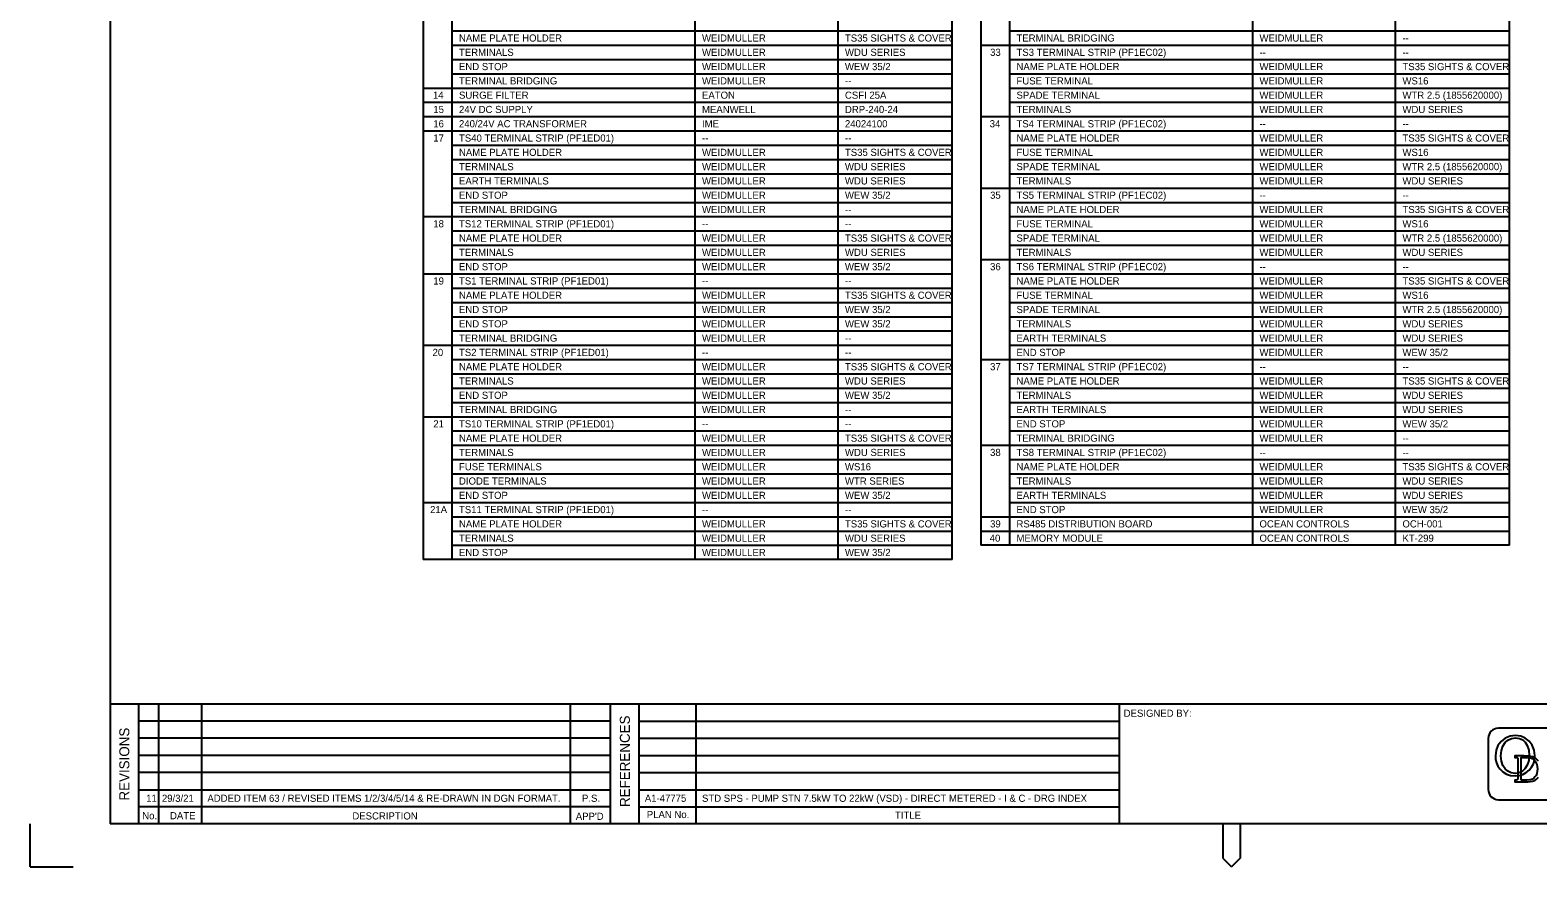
# Model space of a CAD drawing. Extents: x 0 to 841, y 0 to 594.
# Drawn here: x 0 to 527, y 0 to 293 of the extents above; entities that cross this region are included whole.
import ezdxf

# ---------------------------------------------------------------- set-up
doc = ezdxf.new("R2010")
doc.units = 0
for name, color, linetype in [('A1BORDER', 7, 'Continuous'), ('Default', 7, 'Continuous'), ('Level 1', 7, 'Continuous'), ('Level 10', 7, 'Continuous')]:
    doc.layers.add(name, color=color, linetype=linetype)

msp = doc.modelspace()

# ---------------------------------------------------------------- linework, layer by layer
at = {"layer": 'A1BORDER'}
for p, q in [((28, 581), (28, 15)), ((28, 57), (829, 57)), ((38, 15), (38, 57)), ((45, 15), (45, 57)), ((60, 15), (60, 57)), ((189, 15), (189, 57)), ((203, 15), (203, 57)), ((213, 15), (213, 57)), ((233, 15), (233, 57)), ((381, 15), (381, 57)), ((203, 51), (38, 51)), ((213, 51), (381, 51)), ((203, 45), (38, 45)), ((213, 45), (381, 45)), ((203, 39), (38, 39)), ((213, 39), (381, 39)), ((203, 33), (38, 33)), ((213, 33), (381, 33)), ((38, 27), (203, 27)), ((213, 27), (381, 27)), ((203, 21), (38, 21)), ((213, 21), (381, 21)), ((0, 0), (0, 15)), ((829, 15), (28, 15)), ((417.19, 15), (417.19, 3)), ((423.19, 15), (423.19, 3)), ((417.19, 3), (420.19, 0)), ((423.19, 3), (420.19, 0)), ((0, 0), (15, 0))]:
    msp.add_line(p, q, dxfattribs=at)
at = {"layer": 'Default'}
for p, q in [((342.5, 292.5), (517.5, 292.5)), ((332.5, 287.5), (517.5, 287.5)), ((342.5, 282.5), (517.5, 282.5)), ((342.5, 277.5), (517.5, 277.5)), ((342.5, 272.5), (517.5, 272.5)), ((342.5, 267.5), (517.5, 267.5)), ((332.5, 262.5), (517.5, 262.5)), ((342.5, 257.5), (517.5, 257.5)), ((342.5, 252.5), (517.5, 252.5)), ((342.5, 247.5), (517.5, 247.5)), ((332.5, 237.5), (517.5, 237.5)), ((342.5, 242.5), (517.5, 242.5)), ((342.5, 232.5), (517.5, 232.5)), ((342.5, 227.5), (517.5, 227.5)), ((342.5, 222.5), (517.5, 222.5)), ((342.5, 217.5), (517.5, 217.5)), ((332.5, 212.5), (517.5, 212.5)), ((342.5, 207.5), (517.5, 207.5)), ((342.5, 202.5), (517.5, 202.5)), ((342.5, 197.5), (517.5, 197.5)), ((342.5, 192.5), (517.5, 192.5)), ((342.5, 187.5), (517.5, 187.5)), ((342.5, 182.5), (517.5, 182.5)), ((332.5, 177.5), (517.5, 177.5)), ((342.5, 172.5), (517.5, 172.5)), ((342.5, 167.5), (517.5, 167.5)), ((342.5, 162.5), (517.5, 162.5)), ((342.5, 157.5), (517.5, 157.5)), ((342.5, 152.5), (517.5, 152.5)), ((332.5, 147.5), (517.5, 147.5)), ((342.5, 142.5), (517.5, 142.5)), ((342.5, 137.5), (517.5, 137.5)), ((342.5, 132.5), (517.5, 132.5)), ((342.5, 127.5), (517.5, 127.5))]:
    msp.add_line(p, q, dxfattribs=at)
at = {"layer": 'Level 1'}
for p, q in [((137.5, 546), (137.5, 107.5)), ((322.5, 107.5), (322.5, 546)), ((332.5, 546), (332.5, 112.5)), ((517.5, 112.5), (517.5, 546)), ((147.5, 536.25), (147.5, 107.5)), ((232.5, 536.25), (232.5, 107.5)), ((282.5, 536.25), (282.5, 107.5)), ((342.5, 536.25), (342.5, 112.5)), ((427.5, 536.25), (427.5, 112.5)), ((477.5, 536.25), (477.5, 112.5)), ((147.5, 292.5), (322.5, 292.5)), ((147.5, 287.5), (322.5, 287.5)), ((147.5, 282.5), (322.5, 282.5)), ((147.5, 277.5), (322.5, 277.5)), ((137.5, 272.5), (322.5, 272.5)), ((137.5, 267.5), (322.5, 267.5)), ((137.5, 262.5), (322.5, 262.5)), ((137.5, 257.5), (322.5, 257.5)), ((147.5, 252.5), (322.5, 252.5)), ((147.5, 247.5), (322.5, 247.5)), ((147.5, 242.5), (322.5, 242.5)), ((147.5, 237.5), (322.5, 237.5)), ((147.5, 232.5), (322.5, 232.5)), ((137.5, 227.5), (322.5, 227.5)), ((147.5, 222.5), (322.5, 222.5)), ((147.5, 217.5), (322.5, 217.5)), ((147.5, 212.5), (322.5, 212.5)), ((137.5, 207.5), (322.5, 207.5)), ((147.5, 202.5), (322.5, 202.5)), ((147.5, 197.5), (322.5, 197.5)), ((147.5, 192.5), (322.5, 192.5)), ((147.5, 187.5), (322.5, 187.5)), ((137.5, 182.5), (322.5, 182.5)), ((147.5, 177.5), (322.5, 177.5)), ((147.5, 172.5), (322.5, 172.5)), ((147.5, 167.5), (322.5, 167.5)), ((147.5, 162.5), (322.5, 162.5)), ((137.5, 157.5), (322.5, 157.5)), ((147.5, 152.5), (322.5, 152.5)), ((147.5, 147.5), (322.5, 147.5)), ((147.5, 142.5), (322.5, 142.5)), ((147.5, 137.5), (322.5, 137.5)), ((147.5, 132.5), (322.5, 132.5)), ((137.5, 127.5), (322.5, 127.5)), ((147.5, 122.5), (322.5, 122.5)), ((332.5, 122.5), (517.5, 122.5)), ((147.5, 117.5), (322.5, 117.5)), ((332.5, 117.5), (517.5, 117.5)), ((147.5, 112.5), (322.5, 112.5)), ((517.5, 112.5), (332.5, 112.5)), ((322.5, 107.5), (137.5, 107.5))]:
    msp.add_line(p, q, dxfattribs=at)
for points in [[(519.59, 45.93), (517.69, 45.7), (515.96, 45), (514.48, 43.9), (513.4, 42.47), (512.73, 40.77), (512.5, 38.87), (512.6, 37.57), (512.9, 36.37), (513.39, 35.25), (514.1, 34.25), (515.17, 33.2), (516.4, 32.45), (517.82, 32), (519.4, 31.87), (520.84, 32), (522.14, 32.35), (523.32, 32.97), (524.34, 33.83), (525.19, 34.9), (525.8, 36.1), (526.17, 37.45), (526.28, 38.95), (526.07, 40.85), (525.42, 42.53), (524.37, 43.93), (522.94, 45.03), (521.36, 45.7)], [(519.6, 45.1), (520.96, 44.93), (522.06, 44.45), (522.96, 43.63), (523.66, 42.47), (524.18, 40.8), (524.36, 39), (524.18, 37.23), (523.66, 35.63), (522.86, 34.3), (521.88, 33.4), (520.73, 32.87), (519.42, 32.7), (518.08, 32.87), (516.88, 33.43), (515.88, 34.3), (515.1, 35.5), (514.59, 37), (514.43, 38.83), (514.59, 40.7), (515.1, 42.27), (515.89, 43.5), (516.9, 44.37), (518.14, 44.93)], [(521.52, 30.35), (521.52, 38.25), (522.88, 38.25), (524.09, 38.23), (524.74, 38.1), (525.32, 37.87), (525.84, 37.53), (526.32, 37.05), (526.7, 36.5), (526.99, 35.85), (527.16, 35.13), (527.22, 34.27), (527.16, 33.43), (526.99, 32.67), (526.72, 32), (526.36, 31.45), (525.93, 31.03), (525.5, 30.73), (524.52, 30.45), (523.5, 30.35)]]:
    msp.add_lwpolyline(points, close=True, dxfattribs=at)
msp.add_lwpolyline([(527.62, 37), (527.18, 37.5), (526.7, 37.95), (526.16, 38.27), (525.54, 38.53), (524.36, 38.73), (522.5, 38.8), (519.3, 38.8), (519.3, 38.25), (520.07, 38.23), (520.34, 38), (520.4, 37.5), (520.4, 31.07), (520.36, 30.63), (520.16, 30.43), (519.78, 30.35), (519.67, 30.35), (519.3, 30.35), (519.3, 29.8), (523.88, 29.8), (524.7, 29.85), (525.53, 30), (526.28, 30.25), (526.93, 30.67), (527.56, 31.33)], dxfattribs=at)
at = {"layer": 'Level 10'}
for p, q in [((571.47, 48.5), (513.54, 48.5)), ((510, 44.97), (510, 27.03)), ((513.54, 23.5), (571.47, 23.5)), ((513.54, 23.5), (513.54, 23.5))]:
    msp.add_line(p, q, dxfattribs=at)
for centre, start, end in [((513.54, 44.96), 90, 180), ((513.54, 27.03), 180, 270)]:
    msp.add_arc(centre, 3.54, start, end, dxfattribs=at)

# ---------------------------------------------------------------- texts
at = {"layer": 'A1BORDER'}
for s, p in [('DESIGNED BY:', (382.5, 52.5)), ('No.', (39.21, 16.65)), ('DATE', (48.92, 16.65)), ('DESCRIPTION', (112.71, 16.57)), ("APP'D", (190.85, 16.44)), ('PLAN No.', (215.69, 17.06)), ('TITLE', (302.5, 16.81))]:
    msp.add_text(s, height=2.5, dxfattribs=at).set_placement(p)
for s, p in [('REVISIONS', (34.68, 23.2)), ('REFERENCES', (209.76, 20.96))]:
    msp.add_text(s, height=3.5, rotation=90, dxfattribs=at).set_placement(p)
at = {"layer": 'Default'}
for s, p in [('TERMINAL BRIDGING', (345, 288.75)), ('WEIDMULLER', (430, 288.75)), ('33', (335.76, 283.75)), ('TS3 TERMINAL STRIP (PF1EC02)', (345, 283.75)), ('--', (430, 283.75)), ('--', (480, 288.75)), ('--', (480, 283.75)), ('NAME PLATE HOLDER', (345, 278.75)), ('WEIDMULLER', (430, 278.75)), ('TS35 SIGHTS & COVER', (480, 278.75)), ('FUSE TERMINAL', (345, 273.75)), ('WEIDMULLER', (430, 273.75)), ('WS16', (480, 273.75)), ('SPADE TERMINAL', (345, 268.75)), ('WEIDMULLER', (430, 268.75)), ('WTR 2.5 (1855620000)', (480, 268.75)), ('TERMINALS', (345, 263.75)), ('WEIDMULLER', (430, 263.75)), ('WDU SERIES', (480, 263.75)), ('34', (335.63, 258.75)), ('TS4 TERMINAL STRIP (PF1EC02)', (345, 258.75)), ('--', (430, 258.75)), ('--', (480, 258.75)), ('NAME PLATE HOLDER', (345, 253.75)), ('WEIDMULLER', (430, 253.75)), ('TS35 SIGHTS & COVER', (480, 253.75)), ('FUSE TERMINAL', (345, 248.75)), ('WEIDMULLER', (430, 248.75)), ('WS16', (480, 248.75)), ('SPADE TERMINAL', (345, 243.75)), ('WEIDMULLER', (430, 243.75)), ('WTR 2.5 (1855620000)', (480, 243.75)), ('TERMINALS', (345, 238.75)), ('WEIDMULLER', (430, 238.75)), ('WDU SERIES', (480, 238.75)), ('35', (335.76, 233.75)), ('TS5 TERMINAL STRIP (PF1EC02)', (345, 233.75)), ('--', (430, 233.75)), ('--', (480, 233.75)), ('NAME PLATE HOLDER', (345, 228.75)), ('WEIDMULLER', (430, 228.75)), ('TS35 SIGHTS & COVER', (480, 228.75)), ('FUSE TERMINAL', (345, 223.75)), ('WEIDMULLER', (430, 223.75)), ('WS16', (480, 223.75)), ('TERMINALS', (345, 213.75)), ('SPADE TERMINAL', (345, 218.75)), ('WEIDMULLER', (430, 218.75)), ('WEIDMULLER', (430, 213.75)), ('WTR 2.5 (1855620000)', (480, 218.75)), ('WDU SERIES', (480, 213.75)), ('36', (335.76, 208.75)), ('TS6 TERMINAL STRIP (PF1EC02)', (345, 208.75)), ('NAME PLATE HOLDER', (345, 203.75)), ('WEIDMULLER', (430, 203.75)), ('--', (430, 208.75)), ('TS35 SIGHTS & COVER', (480, 203.75)), ('--', (480, 208.75)), ('FUSE TERMINAL', (345, 198.75)), ('WEIDMULLER', (430, 198.75)), ('WS16', (480, 198.75)), ('SPADE TERMINAL', (345, 193.75)), ('WEIDMULLER', (430, 193.75)), ('WTR 2.5 (1855620000)', (480, 193.75)), ('TERMINALS', (345, 188.75)), ('WEIDMULLER', (430, 188.75)), ('WDU SERIES', (480, 188.75)), ('EARTH TERMINALS', (345, 183.75)), ('WEIDMULLER', (430, 183.75)), ('WDU SERIES', (480, 183.75)), ('END STOP', (345, 178.75)), ('WEIDMULLER', (430, 178.75)), ('WEW 35/2', (480, 178.75)), ('37', (335.76, 173.75)), ('TS7 TERMINAL STRIP (PF1EC02)', (345, 173.75)), ('--', (430, 173.75)), ('--', (480, 173.75)), ('NAME PLATE HOLDER', (345, 168.75)), ('WEIDMULLER', (430, 168.75)), ('TS35 SIGHTS & COVER', (480, 168.75)), ('TERMINALS', (345, 163.75)), ('WEIDMULLER', (430, 163.75)), ('WDU SERIES', (480, 163.75)), ('EARTH TERMINALS', (345, 158.75)), ('WEIDMULLER', (430, 158.75)), ('WDU SERIES', (480, 158.75)), ('END STOP', (345, 153.75)), ('WEIDMULLER', (430, 153.75)), ('WEW 35/2', (480, 153.75)), ('TERMINAL BRIDGING', (345, 148.75)), ('WEIDMULLER', (430, 148.75)), ('--', (480, 148.75)), ('38', (335.76, 143.75)), ('TS8 TERMINAL STRIP (PF1EC02)', (345, 143.75)), ('--', (430, 143.75)), ('--', (480, 143.75)), ('NAME PLATE HOLDER', (345, 138.75)), ('WEIDMULLER', (430, 138.75)), ('TS35 SIGHTS & COVER', (480, 138.75)), ('TERMINALS', (345, 133.75)), ('WEIDMULLER', (430, 133.75)), ('WDU SERIES', (480, 133.75)), ('EARTH TERMINALS', (345, 128.75)), ('WEIDMULLER', (430, 128.75)), ('WDU SERIES', (480, 128.75)), ('END STOP', (345, 123.75)), ('WEIDMULLER', (430, 123.75)), ('WEW 35/2', (480, 123.75)), ('40', (335.63, 113.75))]:
    msp.add_text(s, height=2.5, dxfattribs=at).set_placement(p)
at = {"layer": 'Level 1'}
for s, p in [('NAME PLATE HOLDER', (150, 288.75)), ('WEIDMULLER', (235, 288.75)), ('TS35 SIGHTS & COVER', (285, 288.75)), ('TERMINALS', (150, 283.75)), ('WEIDMULLER', (235, 283.75)), ('WDU SERIES', (285, 283.75)), ('END STOP', (150, 278.75)), ('WEIDMULLER', (235, 278.75)), ('WEW 35/2', (285, 278.75)), ('TERMINAL BRIDGING', (150, 273.75)), ('WEIDMULLER', (235, 273.75)), ('--', (285, 273.75)), ('14', (140.88, 268.75)), ('SURGE FILTER', (150, 268.75)), ('EATON', (235, 268.75)), ('CSFI 25A', (285, 268.75)), ('15', (141.01, 263.75)), ('24V DC SUPPLY', (150, 263.75)), ('MEANWELL', (235, 263.75)), ('DRP-240-24', (285, 263.75)), ('16', (141.01, 258.75)), ('240/24V AC TRANSFORMER', (150, 258.75)), ('IME', (235, 258.75)), ('24024100', (285, 258.75)), ('17', (141.01, 253.75)), ('TS40 TERMINAL STRIP (PF1ED01)', (150, 253.75)), ('--', (235, 253.75)), ('--', (285, 253.75)), ('NAME PLATE HOLDER', (150, 248.75)), ('WEIDMULLER', (235, 248.75)), ('TS35 SIGHTS & COVER', (285, 248.75)), ('TERMINALS', (150, 243.75)), ('WEIDMULLER', (235, 243.75)), ('WDU SERIES', (285, 243.75)), ('EARTH TERMINALS', (150, 238.75)), ('WEIDMULLER', (235, 238.75)), ('WDU SERIES', (285, 238.75)), ('END STOP', (150, 233.75)), ('WEIDMULLER', (235, 233.75)), ('WEW 35/2', (285, 233.75)), ('TERMINAL BRIDGING', (150, 228.75)), ('WEIDMULLER', (235, 228.75)), ('--', (285, 228.75)), ('18', (141.01, 223.75)), ('TS12 TERMINAL STRIP (PF1ED01)', (150, 223.75)), ('--', (235, 223.75)), ('--', (285, 223.75)), ('TERMINALS', (150, 213.75)), ('NAME PLATE HOLDER', (150, 218.75)), ('WEIDMULLER', (235, 218.75)), ('WEIDMULLER', (235, 213.75)), ('WDU SERIES', (285, 213.75)), ('TS35 SIGHTS & COVER', (285, 218.75)), ('END STOP', (150, 208.75)), ('WEIDMULLER', (235, 208.75)), ('WEW 35/2', (285, 208.75)), ('19', (141.01, 203.75)), ('TS1 TERMINAL STRIP (PF1ED01)', (150, 203.75)), ('NAME PLATE HOLDER', (150, 198.75)), ('WEIDMULLER', (235, 198.75)), ('--', (235, 203.75)), ('TS35 SIGHTS & COVER', (285, 198.75)), ('--', (285, 203.75)), ('END STOP', (150, 193.75)), ('WEIDMULLER', (235, 193.75)), ('WEW 35/2', (285, 193.75)), ('END STOP', (150, 188.75)), ('WEIDMULLER', (235, 188.75)), ('WEW 35/2', (285, 188.75)), ('TERMINAL BRIDGING', (150, 183.75)), ('WEIDMULLER', (235, 183.75)), ('--', (285, 183.75)), ('20', (140.76, 178.75)), ('TS2 TERMINAL STRIP (PF1ED01)', (150, 178.75)), ('--', (235, 178.75)), ('--', (285, 178.75)), ('NAME PLATE HOLDER', (150, 173.75)), ('WEIDMULLER', (235, 173.75)), ('TS35 SIGHTS & COVER', (285, 173.75)), ('TERMINALS', (150, 168.75)), ('WEIDMULLER', (235, 168.75)), ('WDU SERIES', (285, 168.75)), ('END STOP', (150, 163.75)), ('WEIDMULLER', (235, 163.75)), ('WEW 35/2', (285, 163.75)), ('TERMINAL BRIDGING', (150, 158.75)), ('WEIDMULLER', (235, 158.75)), ('--', (285, 158.75)), ('21', (141.01, 153.75)), ('TS10 TERMINAL STRIP (PF1ED01)', (150, 153.75)), ('--', (235, 153.75)), ('--', (285, 153.75)), ('NAME PLATE HOLDER', (150, 148.75)), ('WEIDMULLER', (235, 148.75)), ('TS35 SIGHTS & COVER', (285, 148.75)), ('TERMINALS', (150, 143.75)), ('WEIDMULLER', (235, 143.75)), ('WDU SERIES', (285, 143.75)), ('FUSE TERMINALS', (150, 138.75)), ('WEIDMULLER', (235, 138.75)), ('WS16', (285, 138.75)), ('DIODE TERMINALS', (150, 133.75)), ('WEIDMULLER', (235, 133.75)), ('WTR SERIES', (285, 133.75)), ('END STOP', (150, 128.75)), ('WEIDMULLER', (235, 128.75)), ('WEW 35/2', (285, 128.75)), ('21A', (139.89, 123.75)), ('TS11 TERMINAL STRIP (PF1ED01)', (150, 123.75)), ('--', (235, 123.75)), ('--', (285, 123.75)), ('TERMINALS', (150, 113.75)), ('NAME PLATE HOLDER', (150, 118.75)), ('WEIDMULLER', (235, 118.75)), ('WEIDMULLER', (235, 113.75)), ('WDU SERIES', (285, 113.75)), ('TS35 SIGHTS & COVER', (285, 118.75)), ('39', (335.76, 118.75)), ('RS485 DISTRIBUTION BOARD', (345, 118.75)), ('MEMORY MODULE', (345, 113.75)), ('OCEAN CONTROLS', (430, 118.75)), ('OCEAN CONTROLS', (430, 113.75)), ('OCH-001', (480, 118.75)), ('KT-299', (480, 113.75)), ('END STOP', (150, 108.75)), ('WEIDMULLER', (235, 108.75)), ('WEW 35/2', (285, 108.75)), ('11', (40.57, 22.75)), ('29/3/21', (46.09, 22.75)), ('ADDED ITEM 63 / REVISED ITEMS 1/2/3/4/5/14 & RE-DRAWN IN DGN FORMAT.', (62, 22.75)), ('P.S.', (193.02, 22.75)), ('A1-47775', (215, 22.75)), ('STD SPS - PUMP STN 7.5kW TO 22kW (VSD) - DIRECT METERED - I & C - DRG INDEX', (235, 22.75))]:
    msp.add_text(s, height=2.5, dxfattribs=at).set_placement(p)

doc.saveas('drawing.dxf')
